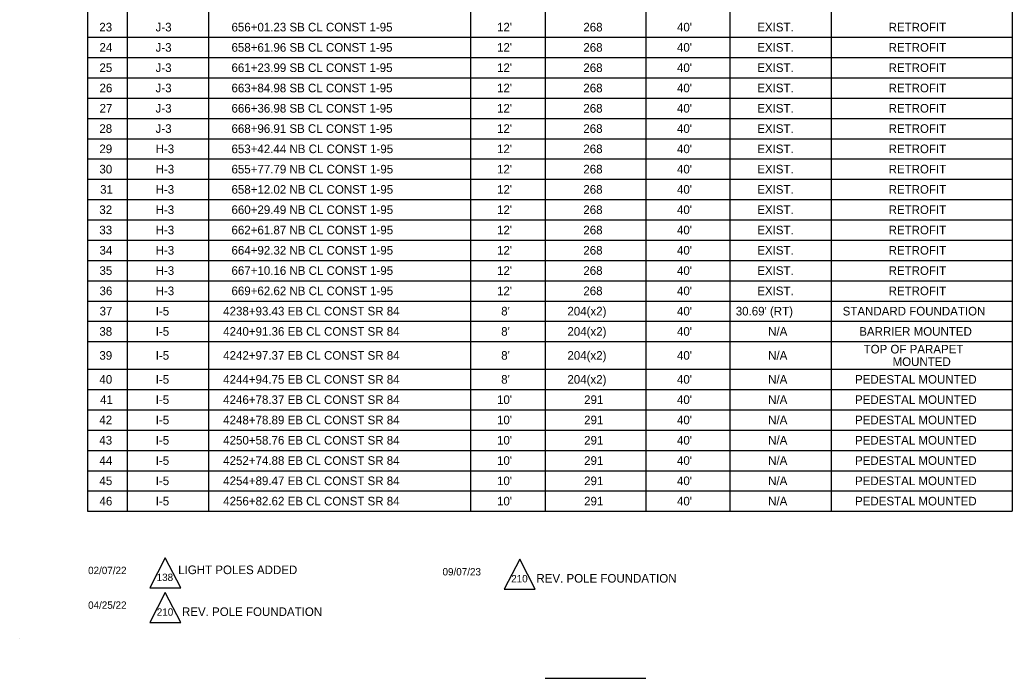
# Model space of a CAD drawing. Extents: x -838.2 to -802.1, y -2200.5 to -2187.7.
# Drawn here: x -818.09 to -810.02, y -2198.43 to -2193.08 of the extents above; entities that cross this region are included whole.
import ezdxf

# ---------------------------------------------------------------- set-up
doc = ezdxf.new("R2010")
doc.units = 0
for name, color, linetype in [('AdhocPoint_dp', 7, 'Continuous'), ('Cloud_dp', 7, 'Continuous'), ('SumBoxBorder_dp', 7, 'Continuous'), ('SumBoxLines_dp', 7, 'Continuous'), ('SumBoxLinesMin_dp', 7, 'Continuous'), ('TextLabel', 7, 'Continuous')]:
    doc.layers.add(name, color=color, linetype=linetype)

msp = doc.modelspace()

# ---------------------------------------------------------------- linework, layer by layer
at = {"layer": 'AdhocPoint_dp'}
msp.add_line((-818.0862, -2198.1071), (-818.0862, -2198.1071), dxfattribs=at)
at = {"layer": 'Cloud_dp'}
for points in [[(-816.9043, -2197.4505), (-817.031, -2197.6945), (-816.7775, -2197.6945)], [(-814.0236, -2197.4613), (-814.1503, -2197.7053), (-813.8968, -2197.7053)], [(-816.9043, -2197.7327), (-817.031, -2197.9768), (-816.7775, -2197.9768)]]:
    msp.add_lwpolyline(points, close=True, dxfattribs=at)
at = {"layer": 'SumBoxBorder_dp'}
for p, q in [((-817.5362, -2187.7197), (-817.5362, -2197.0722)), ((-810.0212, -2187.7197), (-810.0212, -2197.0722)), ((-810.0212, -2187.7197), (-810.0212, -2197.0722)), ((-817.5362, -2197.0722), (-810.0212, -2197.0722)), ((-816.5537, -2197.0722), (-814.4237, -2197.0722))]:
    msp.add_line(p, q, dxfattribs=at)
at = {"layer": 'SumBoxLines_dp'}
for p, q in [((-817.2137, -2188.0497), (-817.2137, -2197.0722)), ((-817.2137, -2188.0497), (-817.2137, -2197.0722)), ((-816.5537, -2188.0497), (-816.5537, -2197.0722)), ((-816.5537, -2188.0497), (-816.5537, -2197.0722)), ((-814.4237, -2188.0497), (-814.4237, -2195.0322)), ((-814.4237, -2188.0497), (-814.4237, -2197.0722)), ((-813.8162, -2188.0497), (-813.8162, -2197.0722)), ((-813.8162, -2188.0497), (-813.8162, -2197.0722)), ((-812.9987, -2188.0497), (-812.9987, -2197.0722)), ((-812.9987, -2188.0497), (-812.9987, -2197.0722)), ((-812.3162, -2188.0497), (-812.3162, -2197.0722)), ((-812.3162, -2188.0497), (-812.3162, -2197.0722)), ((-811.4912, -2188.0497), (-811.4912, -2197.0722)), ((-811.4912, -2188.0497), (-811.4912, -2197.0722)), ((-814.4237, -2195.1972), (-814.4237, -2197.0722))]:
    msp.add_line(p, q, dxfattribs=at)
at = {"layer": 'SumBoxLinesMin_dp'}
for p, q in [((-817.5362, -2193.2172), (-810.0212, -2193.2172)), ((-817.5362, -2193.2172), (-810.0212, -2193.2172)), ((-817.5362, -2193.3822), (-810.0212, -2193.3822)), ((-817.5362, -2193.3822), (-810.0212, -2193.3822)), ((-817.5362, -2193.5472), (-810.0212, -2193.5472)), ((-817.5362, -2193.5472), (-810.0212, -2193.5472)), ((-817.5362, -2193.7122), (-810.0212, -2193.7122)), ((-817.5362, -2193.7122), (-810.0212, -2193.7122)), ((-817.5362, -2193.8772), (-810.0212, -2193.8772)), ((-817.5362, -2193.8772), (-810.0212, -2193.8772)), ((-817.5362, -2194.0422), (-810.0212, -2194.0422)), ((-817.5362, -2194.0422), (-810.0212, -2194.0422)), ((-817.5362, -2194.2072), (-810.0212, -2194.2072)), ((-817.5362, -2194.2072), (-810.0212, -2194.2072)), ((-817.5362, -2194.3722), (-810.0212, -2194.3722)), ((-817.5362, -2194.3722), (-810.0212, -2194.3722)), ((-817.5362, -2194.5372), (-810.0212, -2194.5372)), ((-817.5362, -2194.5372), (-810.0212, -2194.5372)), ((-817.5362, -2194.7022), (-810.0212, -2194.7022)), ((-817.5362, -2194.7022), (-810.0212, -2194.7022)), ((-817.5362, -2194.8672), (-810.0212, -2194.8672)), ((-817.5362, -2194.8672), (-810.0212, -2194.8672)), ((-817.5362, -2195.0322), (-810.0212, -2195.0322)), ((-817.5362, -2195.0322), (-810.0212, -2195.0322)), ((-817.5362, -2195.1972), (-816.5537, -2195.1972)), ((-817.5362, -2195.1972), (-810.0212, -2195.1972)), ((-814.4237, -2195.1972), (-810.0212, -2195.1972)), ((-817.5362, -2195.3622), (-810.0212, -2195.3622)), ((-817.5362, -2195.3622), (-810.0212, -2195.3622)), ((-817.5362, -2195.5272), (-810.0212, -2195.5272)), ((-817.5362, -2195.5272), (-810.0212, -2195.5272)), ((-817.5362, -2195.6922), (-810.0212, -2195.6922)), ((-817.5362, -2195.6922), (-810.0212, -2195.6922)), ((-817.5362, -2195.9172), (-810.0212, -2195.9172)), ((-817.5362, -2195.9172), (-810.0212, -2195.9172)), ((-817.5362, -2196.0822), (-810.0212, -2196.0822)), ((-817.5362, -2196.0822), (-810.0212, -2196.0822)), ((-817.5362, -2196.2472), (-810.0212, -2196.2472)), ((-817.5362, -2196.2472), (-810.0212, -2196.2472)), ((-817.5362, -2196.4122), (-810.0212, -2196.4122)), ((-817.5362, -2196.4122), (-810.0212, -2196.4122)), ((-817.5362, -2196.5772), (-810.0212, -2196.5772)), ((-817.5362, -2196.5772), (-810.0212, -2196.5772)), ((-817.5362, -2196.7422), (-810.0212, -2196.7422)), ((-817.5362, -2196.7422), (-810.0212, -2196.7422)), ((-817.5362, -2196.9072), (-816.5537, -2196.9072)), ((-817.5362, -2196.9072), (-810.0212, -2196.9072)), ((-814.4237, -2196.9072), (-810.0212, -2196.9072)), ((-817.2137, -2197.0722), (-816.5537, -2197.0722)), ((-814.4237, -2197.0722), (-813.8162, -2197.0722)), ((-811.4912, -2197.0722), (-810.0212, -2197.0722)), ((-813.8162, -2198.4297), (-812.9987, -2198.4297))]:
    msp.add_line(p, q, dxfattribs=at)

# ---------------------------------------------------------------- texts
at = {"layer": 'Cloud_dp'}
for s, p in [('138', (-816.9742, -2197.6395)), ('210', (-814.0925, -2197.6504)), ('210', (-816.9732, -2197.9218))]:
    msp.add_text(s, height=0.05998, rotation=0, dxfattribs=at).set_placement(p)
at = {"layer": 'TextLabel'}
for s, height, p in [('23', 0.07, (-817.4403, -2193.1697)), ('J-3', 0.07, (-816.9829, -2193.1697)), ('656+01.23 SB CL CONST 1-95', 0.07, (-816.3661, -2193.1697)), ("12'", 0.07, (-814.2079, -2193.1697)), ('268', 0.07, (-813.5064, -2193.1697)), ("40'", 0.07, (-812.7454, -2193.1697)), ('EXIST.', 0.07, (-812.093, -2193.1697)), ('RETROFIT', 0.07, (-811.0254, -2193.1697)), ('24', 0.07, (-817.4389, -2193.3347)), ('J-3', 0.07, (-816.9829, -2193.3347)), ('658+61.96 SB CL CONST 1-95', 0.07, (-816.3661, -2193.3347)), ("12'", 0.07, (-814.2079, -2193.3347)), ('268', 0.07, (-813.5064, -2193.3347)), ("40'", 0.07, (-812.7454, -2193.3347)), ('EXIST.', 0.07, (-812.093, -2193.3347)), ('RETROFIT', 0.07, (-811.0254, -2193.3347)), ('25', 0.07, (-817.4393, -2193.4997)), ('J-3', 0.07, (-816.9829, -2193.4997)), ('661+23.99 SB CL CONST 1-95', 0.07, (-816.3661, -2193.4997)), ("12'", 0.07, (-814.2079, -2193.4997)), ('268', 0.07, (-813.5064, -2193.4997)), ("40'", 0.07, (-812.7454, -2193.4997)), ('EXIST.', 0.07, (-812.093, -2193.4997)), ('RETROFIT', 0.07, (-811.0254, -2193.4997)), ('26', 0.07, (-817.4388, -2193.6647)), ('J-3', 0.07, (-816.9829, -2193.6647)), ('663+84.98 SB CL CONST 1-95', 0.07, (-816.3661, -2193.6647)), ("12'", 0.07, (-814.2079, -2193.6647)), ('268', 0.07, (-813.5064, -2193.6647)), ("40'", 0.07, (-812.7454, -2193.6647)), ('EXIST.', 0.07, (-812.093, -2193.6647)), ('RETROFIT', 0.07, (-811.0254, -2193.6647)), ('27', 0.07, (-817.4382, -2193.8297)), ('J-3', 0.07, (-816.9829, -2193.8297)), ('666+36.98 SB CL CONST 1-95', 0.07, (-816.3661, -2193.8297)), ("12'", 0.07, (-814.2079, -2193.8297)), ('268', 0.07, (-813.5064, -2193.8297)), ("40'", 0.07, (-812.7454, -2193.8297)), ('EXIST.', 0.07, (-812.093, -2193.8297)), ('RETROFIT', 0.07, (-811.0254, -2193.8297)), ('28', 0.07, (-817.44, -2193.9947)), ('J-3', 0.07, (-816.9829, -2193.9947)), ('668+96.91 SB CL CONST 1-95', 0.07, (-816.3661, -2193.9947)), ("12'", 0.07, (-814.2079, -2193.9947)), ('268', 0.07, (-813.5064, -2193.9947)), ("40'", 0.07, (-812.7454, -2193.9947)), ('EXIST.', 0.07, (-812.093, -2193.9947)), ('RETROFIT', 0.07, (-811.0254, -2193.9947)), ('29', 0.07, (-817.4398, -2194.1597)), ('H-3', 0.07, (-816.9829, -2194.1597)), ('653+42.44 NB CL CONST 1-95', 0.07, (-816.3661, -2194.1597)), ("12'", 0.07, (-814.2079, -2194.1597)), ('268', 0.07, (-813.5064, -2194.1597)), ("40'", 0.07, (-812.7454, -2194.1597)), ('EXIST.', 0.07, (-812.093, -2194.1597)), ('RETROFIT', 0.07, (-811.0254, -2194.1597)), ('30', 0.07, (-817.4396, -2194.3247)), ('H-3', 0.07, (-816.9829, -2194.3247)), ('655+77.79 NB CL CONST 1-95', 0.07, (-816.3661, -2194.3247)), ("12'", 0.07, (-814.2079, -2194.3247)), ('268', 0.07, (-813.5064, -2194.3247)), ("40'", 0.07, (-812.7454, -2194.3247)), ('EXIST.', 0.07, (-812.093, -2194.3247)), ('RETROFIT', 0.07, (-811.0254, -2194.3247)), ('31', 0.07, (-817.4335, -2194.4897)), ('H-3', 0.07, (-816.9829, -2194.4897)), ('658+12.02 NB CL CONST 1-95', 0.07, (-816.3661, -2194.4897)), ("12'", 0.07, (-814.2079, -2194.4897)), ('268', 0.07, (-813.5064, -2194.4897)), ("40'", 0.07, (-812.7454, -2194.4897)), ('EXIST.', 0.07, (-812.093, -2194.4897)), ('RETROFIT', 0.07, (-811.0254, -2194.4897)), ('32', 0.07, (-817.4402, -2194.6547)), ('H-3', 0.07, (-816.9829, -2194.6547)), ('660+29.49 NB CL CONST 1-95', 0.07, (-816.3661, -2194.6547)), ("12'", 0.07, (-814.2079, -2194.6547)), ('268', 0.07, (-813.5064, -2194.6547)), ("40'", 0.07, (-812.7454, -2194.6547)), ('EXIST.', 0.07, (-812.093, -2194.6547)), ('RETROFIT', 0.07, (-811.0254, -2194.6547)), ('33', 0.07, (-817.4403, -2194.8197)), ('H-3', 0.07, (-816.9829, -2194.8197)), ('662+61.87 NB CL CONST 1-95', 0.07, (-816.3661, -2194.8197)), ("12'", 0.07, (-814.2079, -2194.8197)), ('268', 0.07, (-813.5064, -2194.8197)), ("40'", 0.07, (-812.7454, -2194.8197)), ('EXIST.', 0.07, (-812.093, -2194.8197)), ('RETROFIT', 0.07, (-811.0254, -2194.8197)), ('34', 0.07, (-817.4389, -2194.9847)), ('H-3', 0.07, (-816.9829, -2194.9847)), ('664+92.32 NB CL CONST 1-95', 0.07, (-816.3661, -2194.9847)), ("12'", 0.07, (-814.2079, -2194.9847)), ('268', 0.07, (-813.5064, -2194.9847)), ("40'", 0.07, (-812.7454, -2194.9847)), ('EXIST.', 0.07, (-812.093, -2194.9847)), ('RETROFIT', 0.07, (-811.0254, -2194.9847)), ('35', 0.07, (-817.4393, -2195.1497)), ('H-3', 0.07, (-816.9829, -2195.1497)), ('667+10.16 NB CL CONST 1-95', 0.07, (-816.3661, -2195.1497)), ("12'", 0.07, (-814.2079, -2195.1497)), ('268', 0.07, (-813.5064, -2195.1497)), ("40'", 0.07, (-812.7454, -2195.1497)), ('EXIST.', 0.07, (-812.093, -2195.1497)), ('RETROFIT', 0.07, (-811.0254, -2195.1497)), ('36', 0.07, (-817.4388, -2195.3147)), ('H-3', 0.07, (-816.9829, -2195.3147)), ('669+62.62 NB CL CONST 1-95', 0.07, (-816.3661, -2195.3147)), ("12'", 0.07, (-814.2079, -2195.3147)), ('268', 0.07, (-813.5064, -2195.3147)), ("40'", 0.07, (-812.7454, -2195.3147)), ('EXIST.', 0.07, (-812.093, -2195.3147)), ('RETROFIT', 0.07, (-811.0254, -2195.3147)), ('37', 0.07, (-817.4382, -2195.4797)), ('I-5', 0.07, (-816.982, -2195.4797)), ('4238+93.43 EB CL CONST SR 84', 0.07, (-816.4334, -2195.4797)), ("8'", 0.07, (-814.174, -2195.4797)), ('204(x2)', 0.07, (-813.6359, -2195.4797)), ("40'", 0.07, (-812.7454, -2195.4797)), ("30.69' (RT)", 0.07, (-812.2677, -2195.4797)), ('STANDARD FOUNDATION', 0.07, (-811.3986, -2195.4797)), ('38', 0.07, (-817.44, -2195.6447)), ('I-5', 0.07, (-816.982, -2195.6447)), ('4240+91.36 EB CL CONST SR 84', 0.07, (-816.4334, -2195.6447)), ("8'", 0.07, (-814.174, -2195.6447)), ('204(x2)', 0.07, (-813.6359, -2195.6447)), ("40'", 0.07, (-812.7454, -2195.6447)), ('N/A', 0.07, (-812.0043, -2195.6447)), ('BARRIER MOUNTED', 0.07, (-811.2641, -2195.6447)), ('39', 0.07, (-817.4398, -2195.8397)), ('I-5', 0.07, (-816.982, -2195.8397)), ('4242+97.37 EB CL CONST SR 84', 0.07, (-816.4334, -2195.8397)), ("8'", 0.07, (-814.174, -2195.8397)), ('204(x2)', 0.07, (-813.6359, -2195.8397)), ("40'", 0.07, (-812.7454, -2195.8397)), ('N/A', 0.07, (-812.0043, -2195.8397)), ('TOP OF PARAPET', 0.07, (-811.2287, -2195.7887)), ('MOUNTED', 0.07, (-810.9931, -2195.8907)), ('40', 0.07, (-817.4396, -2196.0347)), ('I-5', 0.07, (-816.982, -2196.0347)), ('4244+94.75 EB CL CONST SR 84', 0.07, (-816.4334, -2196.0347)), ("8'", 0.07, (-814.174, -2196.0347)), ('204(x2)', 0.07, (-813.6359, -2196.0347)), ("40'", 0.07, (-812.7454, -2196.0347)), ('N/A', 0.07, (-812.0043, -2196.0347)), ('PEDESTAL MOUNTED', 0.07, (-811.298, -2196.0347)), ('41', 0.07, (-817.4335, -2196.1997)), ('I-5', 0.07, (-816.982, -2196.1997)), ('4246+78.37 EB CL CONST SR 84', 0.07, (-816.4334, -2196.1997)), ("10'", 0.07, (-814.2079, -2196.1997)), ('291', 0.07, (-813.4999, -2196.1997)), ("40'", 0.07, (-812.7454, -2196.1997)), ('N/A', 0.07, (-812.0043, -2196.1997)), ('PEDESTAL MOUNTED', 0.07, (-811.298, -2196.1997)), ('42', 0.07, (-817.4402, -2196.3647)), ('I-5', 0.07, (-816.982, -2196.3647)), ('4248+78.89 EB CL CONST SR 84', 0.07, (-816.4334, -2196.3647)), ("10'", 0.07, (-814.2079, -2196.3647)), ('291', 0.07, (-813.4999, -2196.3647)), ("40'", 0.07, (-812.7454, -2196.3647)), ('N/A', 0.07, (-812.0043, -2196.3647)), ('PEDESTAL MOUNTED', 0.07, (-811.298, -2196.3647)), ('43', 0.07, (-817.4403, -2196.5297)), ('I-5', 0.07, (-816.982, -2196.5297)), ('4250+58.76 EB CL CONST SR 84', 0.07, (-816.4334, -2196.5297)), ("10'", 0.07, (-814.2079, -2196.5297)), ('291', 0.07, (-813.4999, -2196.5297)), ("40'", 0.07, (-812.7454, -2196.5297)), ('N/A', 0.07, (-812.0043, -2196.5297)), ('PEDESTAL MOUNTED', 0.07, (-811.298, -2196.5297)), ('44', 0.07, (-817.4389, -2196.6947)), ('I-5', 0.07, (-816.982, -2196.6947)), ('4252+74.88 EB CL CONST SR 84', 0.07, (-816.4334, -2196.6947)), ("10'", 0.07, (-814.2079, -2196.6947)), ('291', 0.07, (-813.4999, -2196.6947)), ("40'", 0.07, (-812.7454, -2196.6947)), ('N/A', 0.07, (-812.0043, -2196.6947)), ('PEDESTAL MOUNTED', 0.07, (-811.298, -2196.6947)), ('45', 0.07, (-817.4393, -2196.8597)), ('I-5', 0.07, (-816.982, -2196.8597)), ('4254+89.47 EB CL CONST SR 84', 0.07, (-816.4334, -2196.8597)), ("10'", 0.07, (-814.2079, -2196.8597)), ('291', 0.07, (-813.4999, -2196.8597)), ("40'", 0.07, (-812.7454, -2196.8597)), ('N/A', 0.07, (-812.0043, -2196.8597)), ('PEDESTAL MOUNTED', 0.07, (-811.298, -2196.8597)), ('46', 0.07, (-817.4388, -2197.0247)), ('I-5', 0.07, (-816.982, -2197.0247)), ('4256+82.62 EB CL CONST SR 84', 0.07, (-816.4334, -2197.0247)), ("10'", 0.07, (-814.2079, -2197.0247)), ('291', 0.07, (-813.4999, -2197.0247)), ("40'", 0.07, (-812.7454, -2197.0247)), ('N/A', 0.07, (-812.0043, -2197.0247)), ('PEDESTAL MOUNTED', 0.07, (-811.298, -2197.0247)), ('02/07/22', 0.06, (-817.5315, -2197.5834)), ('LIGHT POLES ADDED', 0.07, (-816.7992, -2197.5835)), ('09/07/23', 0.06, (-814.6508, -2197.5942)), ('REV. POLE FOUNDATION', 0.07, (-813.8877, -2197.6527)), ('04/25/22', 0.06, (-817.5315, -2197.8656)), ('REV. POLE FOUNDATION', 0.07, (-816.7684, -2197.9241))]:
    msp.add_text(s, height=height, dxfattribs=at).set_placement(p)

doc.saveas('drawing.dxf')
